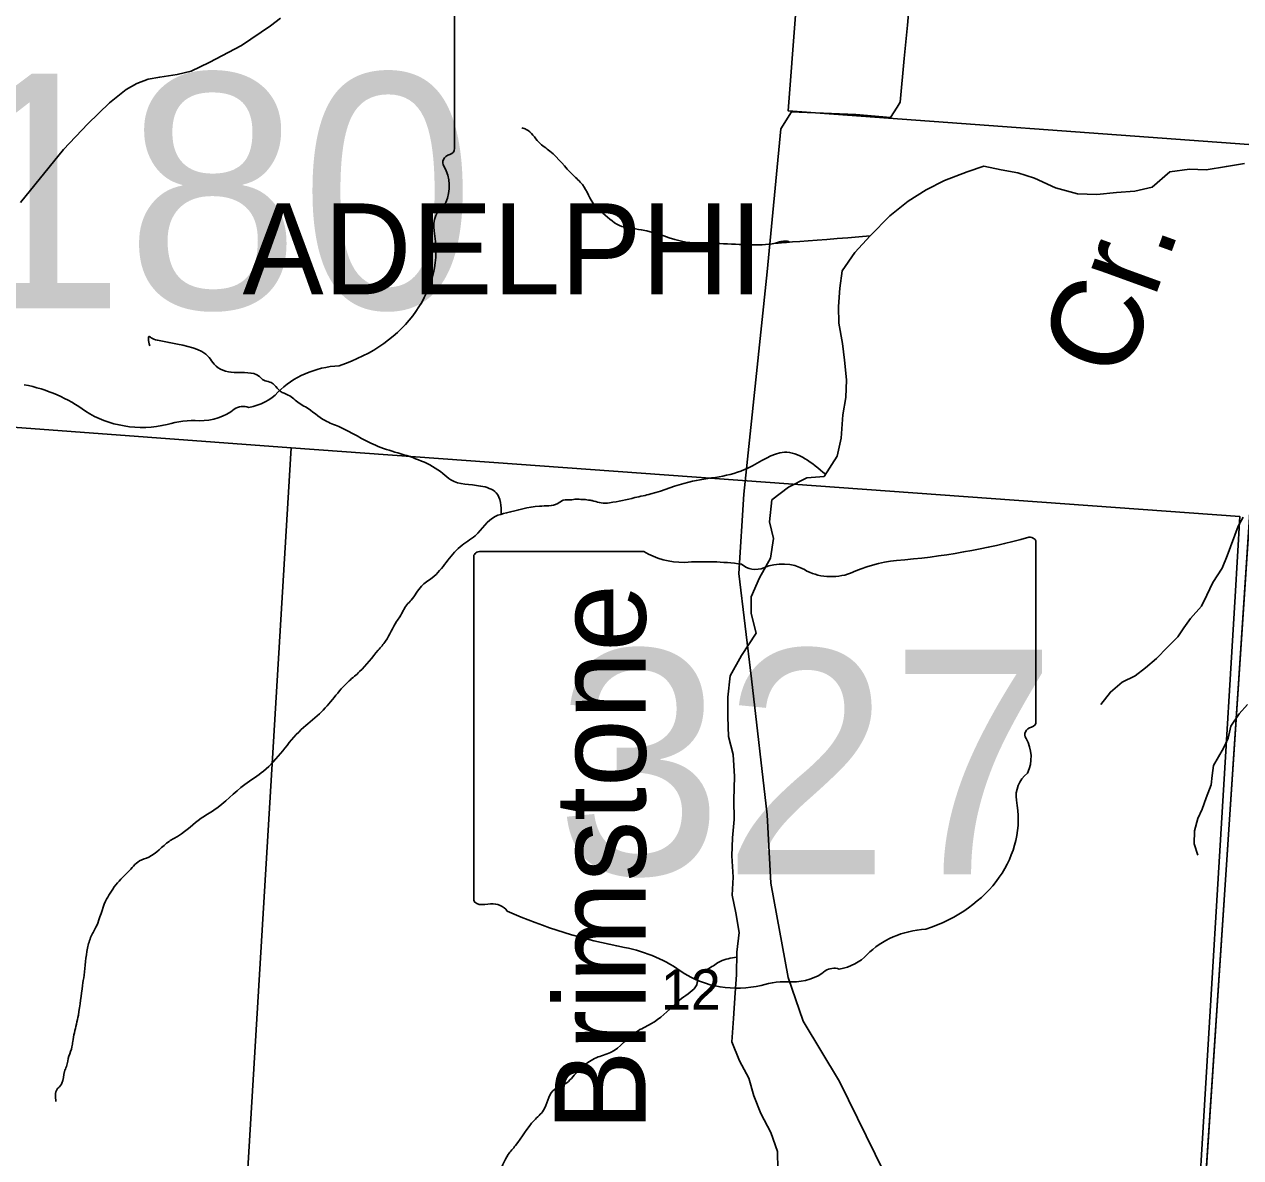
# Model space of a CAD drawing. Extents: x 0 to 42.5, y 0 to 22.
# Drawn here: x 7.502 to 8.135, y 14.815 to 15.405 of the extents above; entities that cross this region are included whole.
import ezdxf

# ---------------------------------------------------------------- set-up
doc = ezdxf.new("R2010")
doc.units = 0
for name, color, linetype in [('GM_X_Corporation', 7, 'Continuous'), ('GM_X_Corporation_Text', 7, 'Continuous'), ('GM_X_Interchange_Ramps', 7, 'Continuous'), ('GM_X_Minor_River', 7, 'Continuous'), ('GM_X_Minor_River_Text', 7, 'Continuous'), ('GM_X_Section', 7, 'Continuous'), ('GM_X_Section_Text', 7, 'Continuous'), ('GM_X_State_Location', 7, 'Continuous'), ('GM_X_State_Route', 7, 'Continuous'), ('GM_X_State_Shield', 7, 'Continuous'), ('SH_Cut_Line', 7, 'Continuous')]:
    doc.layers.add(name, color=color, linetype=linetype)

msp = doc.modelspace()

# ---------------------------------------------------------------- linework, layer by layer
at = {"layer": 'GM_X_Corporation'}
msp.add_lwpolyline([(7.91921, 15.63683), (7.95331, 15.6361), (7.97957, 15.63417), (8.04805, 15.62672), (8.16418, 15.61064), (8.16271, 15.59296), (8.14602, 15.34154), (7.89922, 15.35961), (7.91813, 15.60669)], close=True, dxfattribs=at)
at = {"layer": 'GM_X_Interchange_Ramps'}
msp.add_lwpolyline([(5.08492, 14.1), (8.06989, 14.1), (8.07009, 14.10263), (8.07289, 14.12804), (8.09551, 14.48695), (8.1568, 15.41315), (8.16884, 15.59509), (8.16995, 15.61544), (8.04805, 15.62672), (7.97957, 15.63417), (7.95331, 15.6361), (7.91921, 15.63683), (7.91813, 15.60669), (7.88151, 15.60844), (7.87674, 15.60879), (7.42273, 15.64192), (7.26665, 15.65331), (5.92916, 15.74982)], dxfattribs=at)
msp.add_lwpolyline([(8.06989, 14.1), (8.9, 14.1), (8.9, 15.53758), (8.67633, 15.55354), (8.32394, 15.58239), (8.30432, 15.58399), (8.29687, 15.58461), (8.16884, 15.59509), (8.1568, 15.41315), (8.09551, 14.48695), (8.07289, 14.12804), (8.07009, 14.10263)], close=True, dxfattribs=at)
at = {"layer": 'GM_X_Minor_River'}
for p, q in [((8.13599, 15.14803), (8.13336, 15.14345)), ((8.13813, 15.05054), (8.13393, 15.04564)), ((8.13393, 15.04564), (8.12952, 15.03922)), ((8.12952, 15.03922), (8.12815, 15.03297)), ((8.12815, 15.03297), (8.12569, 15.02785))]:
    msp.add_line(p, q, dxfattribs=at)
for points in [[(7.91787, 15.16935), (7.92472, 15.17982), (7.92668, 15.18928), (7.92752, 15.2014), (7.92909, 15.21048), (7.92953, 15.21957), (7.92846, 15.22981), (7.92739, 15.23854), (7.92557, 15.24916), (7.92525, 15.25788), (7.92607, 15.26735), (7.92727, 15.27643), (7.93376, 15.28586), (7.94175, 15.29452), (7.95203, 15.30506), (7.96153, 15.31257), (7.97103, 15.31857), (7.98051, 15.32343), (7.99226, 15.32789), (8.00098, 15.33086), (8.01004, 15.3289), (8.01872, 15.32732), (8.0274, 15.32461), (8.03833, 15.31961), (8.04965, 15.3165), (8.05985, 15.31604), (8.07007, 15.31711), (8.07952, 15.3178), (8.08861, 15.32001), (8.09774, 15.3279), (8.10796, 15.32935), (8.11665, 15.32891), (8.12725, 15.33073), (8.13671, 15.33217)], [(7.91787, 15.16935), (7.90885, 15.16866), (7.89934, 15.1638), (7.89058, 15.15705), (7.88935, 15.14568), (7.89155, 15.13693), (7.88996, 15.1267), (7.8842, 15.11651), (7.87995, 15.10668), (7.87988, 15.09795), (7.88245, 15.08769), (7.87478, 15.07599), (7.86902, 15.06542), (7.86779, 15.05443), (7.86771, 15.04419), (7.86801, 15.03394), (7.87058, 15.02444), (7.87124, 15.01305), (7.87077, 15.00091), (7.87106, 14.99067), (7.87023, 14.98119), (7.86977, 14.97171), (7.87044, 14.9607), (7.86999, 14.95122), (7.87181, 14.9421), (7.87362, 14.93185), (7.8724, 14.92162), (7.8723, 14.90986), (7.87147, 14.90038), (7.8706, 14.88711), (7.86975, 14.87498), (7.87383, 14.86508), (7.87868, 14.85593), (7.88125, 14.84681), (7.88497, 14.83767), (7.89018, 14.82777), (7.89351, 14.81788), (7.89381, 14.80839)], [(8.13336, 15.14345), (8.12754, 15.128), (8.12509, 15.12154), (8.12018, 15.11413), (8.11697, 15.10748), (8.11434, 15.10178), (8.10848, 15.09532), (8.10508, 15.09056), (8.10187, 15.08581), (8.09658, 15.08048), (8.09091, 15.07459), (8.08505, 15.06964), (8.07975, 15.06545), (8.07294, 15.0622), (8.06689, 15.05706), (8.06179, 15.0506)], [(8.12569, 15.02785), (8.12057, 15.01872), (8.11983, 15.01359), (8.11927, 15.00866), (8.11663, 15.00201), (8.11456, 14.99613), (8.1123, 14.99119), (8.11061, 14.98473), (8.11043, 14.97809), (8.11234, 14.97203)]]:
    msp.add_lwpolyline(points, dxfattribs=at)
for points in [[(7.94175, 15.29452), (7.89829, 15.29137), (7.89961, 15.29154), (7.89678, 15.29177), (7.89413, 15.29124), (7.86355, 15.29054), (7.84581, 15.29136), (7.82264, 15.29774), (7.81133, 15.29998), (7.80157, 15.30749), (7.79838, 15.31056), (7.79204, 15.32124), (7.78717, 15.32622), (7.77517, 15.33868), (7.76935, 15.3433), (7.76279, 15.35001), (7.76053, 15.3508)], [(7.74983, 15.14949), (7.74714, 15.1608), (7.73904, 15.16432), (7.72359, 15.16756), (7.71946, 15.17083), (7.69594, 15.18157), (7.68427, 15.18551), (7.66527, 15.19524), (7.65812, 15.19836), (7.64797, 15.2055), (7.64459, 15.20744), (7.63896, 15.21168), (7.63482, 15.21363), (7.63163, 15.21708), (7.62938, 15.21844), (7.62618, 15.21943), (7.62392, 15.22135), (7.61073, 15.22343), (7.60037, 15.22773), (7.59775, 15.23117), (7.57874, 15.23863), (7.57177, 15.24005), (7.568, 15.24124), (7.56669, 15.2422), (7.56684, 15.23729)], [(7.91859, 15.17045), (7.89715, 15.18192), (7.87822, 15.17368), (7.86328, 15.16917), (7.8474, 15.16637), (7.82773, 15.16022), (7.81941, 15.15826), (7.80618, 15.15561), (7.80184, 15.15548), (7.79807, 15.15648), (7.796, 15.15689), (7.79279, 15.15731), (7.79128, 15.15733), (7.78958, 15.15755), (7.78656, 15.15721), (7.78203, 15.1569), (7.77919, 15.15524), (7.76974, 15.15386), (7.75254, 15.15032), (7.74667, 15.14852), (7.73622, 15.13846), (7.72844, 15.13271), (7.7138, 15.11647), (7.7083, 15.1122), (7.70296, 15.1049), (7.70068, 15.10247), (7.69705, 15.09629), (7.69533, 15.09385), (7.6896, 15.08354), (7.68579, 15.07887), (7.67609, 15.06766), (7.67058, 15.06282), (7.65517, 15.04565), (7.64568, 15.03746), (7.62609, 15.01581), (7.61641, 15.00896), (7.60028, 14.99557), (7.59364, 14.99132), (7.58188, 14.98222), (7.57695, 14.97927), (7.56632, 14.9711), (7.56159, 14.96909), (7.55551, 14.96332), (7.55266, 14.96052), (7.54618, 14.95229), (7.54389, 14.94817), (7.53908, 14.93519), (7.5364, 14.92994), (7.53447, 14.92372), (7.53268, 14.90957), (7.53188, 14.90429), (7.5297, 14.88882), (7.52872, 14.8841), (7.52677, 14.87506), (7.52638, 14.87223), (7.52483, 14.86752), (7.52348, 14.86206), (7.52251, 14.85943), (7.52115, 14.8534), (7.51982, 14.85153), (7.51867, 14.85022), (7.51806, 14.8438)], [(7.87237, 14.91896), (7.8638, 14.91677), (7.85792, 14.91307), (7.85203, 14.90805), (7.85183, 14.90578), (7.84479, 14.89832), (7.84062, 14.89479), (7.82771, 14.8842), (7.82013, 14.88015), (7.80666, 14.86937), (7.79927, 14.86664), (7.79245, 14.8622), (7.78998, 14.85997), (7.7839, 14.85363), (7.77669, 14.84938), (7.77172, 14.83924), (7.76696, 14.83402), (7.75724, 14.82092), (7.75344, 14.81625), (7.74789, 14.80593), (7.74598, 14.80312), (7.74445, 14.80012), (7.74009, 14.79716), (7.73875, 14.79415), (7.73364, 14.79158), (7.72378, 14.78586), (7.71905, 14.78347), (7.70994, 14.7766), (7.69705, 14.76866), (7.69646, 14.76469), (7.69172, 14.7623), (7.68963, 14.76025), (7.68677, 14.75632), (7.68675, 14.75254), (7.68692, 14.75103), (7.68763, 14.74383), (7.68798, 14.73967), (7.6881, 14.73003), (7.68731, 14.72512), (7.68553, 14.71286), (7.68341, 14.70627), (7.67914, 14.6897), (7.67741, 14.68481), (7.67468, 14.67294), (7.67219, 14.66805), (7.66816, 14.65809), (7.66644, 14.65434), (7.66336, 14.64625), (7.66239, 14.64248), (7.66008, 14.63514), (7.65816, 14.6312), (7.65603, 14.62367), (7.65241, 14.61862), (7.65145, 14.61655), (7.64841, 14.613), (7.64517, 14.60832), (7.64346, 14.60627), (7.63849, 14.59858), (7.63224, 14.59489), (7.62576, 14.58534), (7.61059, 14.57497), (7.60868, 14.57273), (7.60603, 14.57088), (7.60204, 14.56734), (7.60089, 14.56509), (7.59612, 14.5576), (7.59173, 14.55123), (7.59, 14.54634), (7.58311, 14.53207), (7.58006, 14.52758), (7.57568, 14.52235), (7.57472, 14.51933), (7.57357, 14.51746), (7.57355, 14.51444), (7.57335, 14.51274), (7.57314, 14.51047), (7.57313, 14.50839), (7.57177, 14.50236), (7.57117, 14.49783), (7.5696, 14.48897)]]:
    msp.add_spline(points, degree=3, dxfattribs=at)
at = {"layer": 'GM_X_Section'}
for points in [[(7.14732, 15.22085), (7.64041, 15.18413), (7.60947, 14.66753), (7.11032, 14.70599)], [(7.64041, 15.18413), (8.13426, 15.14838), (8.13172, 15.10671), (8.10329, 14.63477), (7.60947, 14.66753)]]:
    msp.add_lwpolyline(points, close=True, dxfattribs=at)
at = {"layer": 'GM_X_State_Route'}
for points in [[(7.95958, 15.38697), (7.96119, 15.40436), (7.96454, 15.44253), (7.96671, 15.46671)], [(7.49953, 15.31189), (7.52195, 15.33962), (7.53466, 15.35286), (7.54583, 15.36376), (7.55465, 15.37077), (7.5601, 15.37388), (7.56607, 15.37622), (7.57204, 15.37726), (7.58112, 15.37856), (7.58839, 15.38037), (7.59773, 15.38478), (7.61461, 15.39361), (7.62966, 15.40399), (7.63485, 15.40788)], [(7.95639, 15.36243), (7.95747, 15.36412), (7.95958, 15.38697)], [(8.09562, 14.48668), (8.07838, 14.5234), (8.06257, 14.56131), (8.04603, 14.5905), (8.03955, 14.60681), (8.02681, 14.62955), (8.01442, 14.66406), (7.99785, 14.70691), (7.97748, 14.74994), (7.94913, 14.80681), (7.92591, 14.8542), (7.90692, 14.88559), (7.89914, 14.90842), (7.89013, 14.95748), (7.88826, 14.99303), (7.87997, 15.06389), (7.87343, 15.11876), (7.87611, 15.16005), (7.88825, 15.27582), (7.89524, 15.35037), (7.90085, 15.35924), (7.90385, 15.35911), (7.90485, 15.35906)], [(7.90485, 15.35906), (7.93434, 15.35779), (7.95236, 15.35613), (7.95586, 15.36159), (7.95639, 15.36243)]]:
    msp.add_lwpolyline(points, dxfattribs=at)
at = {"layer": 'GM_X_State_Shield'}
for p, q in [((7.72545, 15.34002), (7.72545, 15.43715)), ((7.72542, 15.34004), (7.72545, 15.34002)), ((8.02811, 15.04172), (8.02811, 15.13464)), ((7.73554, 15.12719), (7.73554, 14.94954)), ((7.8241, 15.13024), (7.73842, 15.13024)), ((8.02808, 15.04174), (8.02811, 15.04172))]:
    msp.add_line(p, q, dxfattribs=at)
for centre, major_axis, start_param, end_param in [((7.72182, 15.33964), (0.00364, 0), 5.05454, 6.418171), ((7.72467, 15.33289), (0.00527, 0), 1.883978, 3.671073), ((7.69115, 15.32061), (0.03163, 0), 5.934695, 6.695948), ((7.73765, 15.29937), (0.02301, 0), 2.387724, 3.262537), ((7.63469, 15.28701), (0.08112, 0), 5.101752, 6.440018), ((7.66889, 15.19154), (0.04443, 0), 1.647645, 2.488434), ((7.48365, 15.16025), (0.07328, 0), 0.823519, 1.323587), ((7.6126, 15.22567), (0.02621, 0), 4.937069, 5.64225), ((7.5629, 15.23204), (0.0465, 0), 4.026481, 4.996735), ((7.59317, 15.21813), (0.02477, 0), 4.691044, 5.507374), ((7.61558, 15.20015), (0.00698, 0), 1.147584, 2.315152), ((7.58977, 15.16784), (0.03821, 0), 1.495662, 1.94098), ((7.9239, 15.37243), (0.31027, 0), 4.814394, 5.042369), ((8.02487, 15.13503), (0.00326, 0), 6.141152, 7.989035), ((7.73889, 15.12756), (0.00339, 0), 1.712693, 3.28349), ((7.84451, 15.15086), (0.03288, 0), 4.042523, 4.731795), ((7.85541, 15.03051), (0.11802, 0), 1.404758, 1.657858), ((7.89613, 15.10795), (0.01972, 0), 0.950623, 2.079405), ((7.96347, 15.07598), (0.06242, 0), 1.699011, 2.107814), ((7.8822, 15.12848), (0.00948, 0), 3.836095, 5.185415), ((7.92158, 15.13611), (0.02372, 0), 4.081561, 5.145723), ((8.02464, 15.04136), (0.00349, 0), 5.05454, 6.418171), ((8.02736, 15.03489), (0.00504, 0), 1.883978, 3.671073), ((7.99529, 15.02315), (0.03026, 0), 5.934695, 6.695948), ((8.03978, 15.00283), (0.02201, 0), 2.387724, 3.262537), ((7.94128, 14.991), (0.07761, 0), 5.101752, 6.440018), ((7.73892, 14.94915), (0.00342, 0), 3.00124, 4.508301), ((7.73944, 14.96732), (0.0261, 0), 4.665946, 4.897461), ((7.74478, 14.93929), (0.00941, 0), 0.519207, 1.627899), ((7.86358, 15.0989), (0.22406, 0), 4.195997, 4.488961), ((7.974, 14.89966), (0.0425, 0), 1.647645, 2.488434), ((7.79678, 14.86973), (0.0701, 0), 0.823519, 1.323587), ((7.92015, 14.93232), (0.02507, 0), 4.937069, 5.64225), ((7.8726, 14.93841), (0.04448, 0), 4.026481, 4.996735), ((7.90155, 14.9251), (0.0237, 0), 4.691044, 5.507374), ((7.92299, 14.9079), (0.00667, 0), 1.147584, 2.315152), ((7.8983, 14.87699), (0.03655, 0), 1.495662, 1.94098)]:
    msp.add_ellipse(centre, major_axis=major_axis, ratio=0.8, start_param=start_param, end_param=end_param, dxfattribs=at)
at = {"layer": 'SH_Cut_Line'}
for points in [[(8.24781, 16.59008), (8.17933, 15.79111), (8.17776, 15.76158), (8.17561, 15.72139), (8.1727, 15.66691), (8.17075, 15.63044), (8.16995, 15.61544), (8.16884, 15.59509), (8.1568, 15.41315), (8.09551, 14.48695), (8.07289, 14.12804), (8.07009, 14.10263), (8.06989, 14.1), (8.9, 14.1), (8.9, 19.05381)], [(2.1, 14.1), (8.06989, 14.1), (8.07009, 14.10263), (8.07289, 14.12804), (8.09551, 14.48695), (8.1568, 15.41315), (8.16884, 15.59509), (8.16995, 15.61544), (8.04805, 15.62672), (7.97957, 15.63417), (7.95331, 15.6361), (7.91921, 15.63683), (7.91813, 15.60669), (7.88151, 15.60844), (7.87674, 15.60879), (7.42273, 15.64192), (7.26665, 15.65331), (5.92916, 15.74982)]]:
    msp.add_lwpolyline(points, dxfattribs=at)

# ---------------------------------------------------------------- texts
at = {"layer": 'GM_X_Corporation_Text'}
msp.add_text('ADELPHI', height=0.047348, rotation=0.00001, dxfattribs=at).set_placement((7.61516, 15.26413))
at = {"layer": 'GM_X_Minor_River_Text'}
for s, rotation, p in [('Cr.', 70.00113, (8.07402, 15.21843)), ('Brimstone', 90.00069, (7.82498, 14.82825))]:
    msp.add_text(s, height=0.047349, rotation=rotation, dxfattribs=at).set_placement(p)
at = {"layer": 'GM_X_Section_Text'}
msp.add_text('12', height=0.020928, rotation=0.00001, dxfattribs=at).set_placement((7.83292, 14.89173))
at = {"layer": 'GM_X_State_Location'}
for s in ['s', 'r']:
    msp.add_text(s, height=0.0000947, dxfattribs=at).set_placement((7.63468, 15.39649))
for s, p in [('180', (7.60125, 15.3896)), ('327', (7.85126, 15.00835))]:
    msp.add_text(s, height=0.0000947, rotation=0.00001, dxfattribs=at).set_placement(p)
at = {"layer": 'GM_X_State_Shield'}
for s, height, p in [('180', 0.122327, (7.46321, 15.25676)), ('327', 0.117031, (7.77802, 14.96207))]:
    msp.add_text(s, height=height, dxfattribs=at).set_placement(p)

doc.saveas('drawing.dxf')
